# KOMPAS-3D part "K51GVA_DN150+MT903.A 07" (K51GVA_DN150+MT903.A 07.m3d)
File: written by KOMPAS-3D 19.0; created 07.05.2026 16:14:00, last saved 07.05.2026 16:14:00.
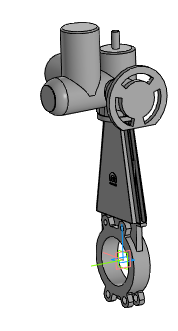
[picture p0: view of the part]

Document properties: Автор: Энергия; Полное имя файла: ..\K51GVA_DN50-DN1000+MT903.A\K51GVA_DN150+MT903.A 07.a3d

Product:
- Part/product: K51GVA_DN150+MT903.A 07
    Масса: 82.0919

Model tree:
1. Операция без истории:1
